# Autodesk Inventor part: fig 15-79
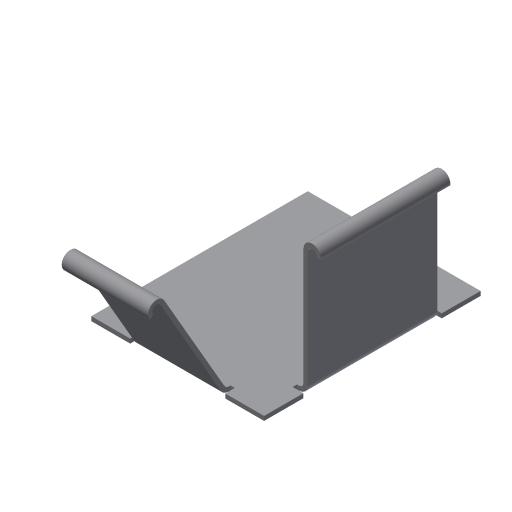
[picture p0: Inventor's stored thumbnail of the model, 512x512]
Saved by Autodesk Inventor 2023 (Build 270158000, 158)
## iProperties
Created: 2002-04
Part Number: fig 15-79
Document SubType Name: Sheet Metal
Density: 1 g/cm^3
Sheet Metal Rule: Default
Material: Generic
Appearance: Default
Control State: 0
Master: False
Checked Out: False
Shininess: 77.0
Angle Display Precision: 2
Document Length Units: 11269
Document Angle Units: 11279
Document Time Units: 11290
Document Mass Units: 11283
Document Length Units Precision: 3
Document Angle Units Precision: 2
Compacted: True
Density: 0.0
Volumn: 0.0
Area: 0.0
PropertySet Name: Model Information
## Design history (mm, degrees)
node "Face1"
  sketch "Sketch1"
    geometry: L1 (-17.882, 11.882)-(2.118, 11.882); L2 (2.118, 11.882)-(2.118, -13.176); L3 (2.118, -13.176)-(-17.882, -13.176); L4 (-17.882, -13.176)-(-17.882, 11.882)
    constraints: 8 end point, 2 parallel, 1 horizontal, 1 perpendicular
    dimensions: "d17" = 20 distance of L2.end L3.end
node "Flange2"
node "Flange3"
feature "Hem8" dims "d82" = 0.5 (= BendReliefWidth), "d83" = 0.25 (= BendReliefDepth), "d84" = 1 (= MinimumRemnant), "d85" = 0.5 (= BendRadius), "d102" = 190 deg, "d103" = 0.5 (= BendRadius), "d104" = 0.5 (= d103), "d108" = 0.5 (= Thickness), "SeamGap" = 0.01
feature "Hem9" dims "d89" = 0.5 (= BendReliefWidth), "d90" = 0.25 (= BendReliefDepth), "d91" = 1 (= MinimumRemnant), "d92" = 0.5 (= BendRadius), "d105" = 190 deg, "d106" = 0.5 (= BendRadius), "d107" = 0.5 (= d106), "d108" = 0.5 (= Thickness), "SeamGap" = 0.01
body "Solid1"
face "Plate1" dims "d108" = 0.5 (= Thickness)
sketch "Sketch3"
  geometry: L1 (5, 0)-(20, 0); L2 (20, 0)-(20, 15); L3 (20, 15)-(5, 15); L4 (5, 15)-(5, 0)
  constraints: 8 end point
face "Plate3" dims "d6" = 15, "d7" = 90 deg, "d8" = 0.5 (= BendRadius), "d18" = 5, "d19" = 15, "d108" = 0.5 (= Thickness), "MinimumRemnant" = 1 (= 2 x Thickness), "BendReliefWidth" = 0.5 (= Thickness)
bend "Bend2" dims "d6" = 15, "d7" = 90 deg, "d8" = 0.5 (= BendRadius), "d56" = 0.5 (= BendReliefWidth), "d57" = 0.25 (= BendReliefDepth), "d58" = 1 (= MinimumRemnant), "d108" = 0.5 (= Thickness), "SeamGap" = 0.01, "MinimumRemnant" = 1 (= 2 x Thickness), "BendReliefWidth" = 0.5 (= Thickness), "TransitionRadius" = 0.5 (= BendRadius)
sketch "Sketch6"
  geometry: L1 (15, 0)-(5, 0); L2 (5, 0)-(5, 15); L3 (5, 15)-(15, 15); L4 (15, 15)-(15, 0)
  constraints: 8 end point
face "Plate4" dims "d20" = 5, "d21" = 10, "d23" = 15, "d24" = 60 deg, "d25" = 0.5 (= BendRadius), "d108" = 0.5 (= Thickness), "MinimumRemnant" = 1 (= 2 x Thickness), "BendReliefWidth" = 0.5 (= Thickness)
bend "Bend3" dims "d22" = 0.5 (= BendRadius), "d23" = 15, "d24" = 60 deg, "d25" = 0.5 (= BendRadius), "d59" = 0.5 (= BendReliefWidth), "d60" = 0.25 (= BendReliefDepth), "d61" = 1 (= MinimumRemnant), "d108" = 0.5 (= Thickness), "SeamGap" = 0.01, "MinimumRemnant" = 1 (= 2 x Thickness), "BendReliefWidth" = 0.5 (= Thickness)
sketch "Sketch12"
  geometry: L1 (0.433, 0.25)-(0, 0); L2 (-0.816, -0.571)-(-1.199, -0.893); A1 r 0.5 centre (-0.433, -0.25) between (0, 0) and (-0.816, -0.571); A2 r 1 centre (-0.433, -0.25) between (0.433, 0.25) and (-1.199, -0.893); 2 further points
  constraints: 4 end point, 4 point on circle
sketch "Sketch13"
  geometry: L1 (0.5, 0)-(0, 0); L2 (-0.992, -0.087)-(-1.485, -0.174); A1 r 0.5 centre (-0.5, 0) between (0, 0) and (-0.992, -0.087); A2 r 1 centre (-0.5, 0) between (0.5, 0) and (-1.485, -0.174); 2 further points
  constraints: 4 end point, 4 point on circle
other parameters: "Thickness" = 0.5, "BendRadius" = 0.5 (= Thickness), "BendReliefDepth" = 0.25 (= 0.5 x Thickness), "CornerReliefSize" = 2 (= 4 x Thickness), "d0" = 0.5 (= BendRadius), "d5" = 0.5 (= BendRadius), "d26" = 0.5 (= BendRadius), "d30" = 0.5 (= BendRadius), "JacobiRadiusSize" = 0.5 (= Thickness), "GapSize" = 0.5 (= Thickness)
